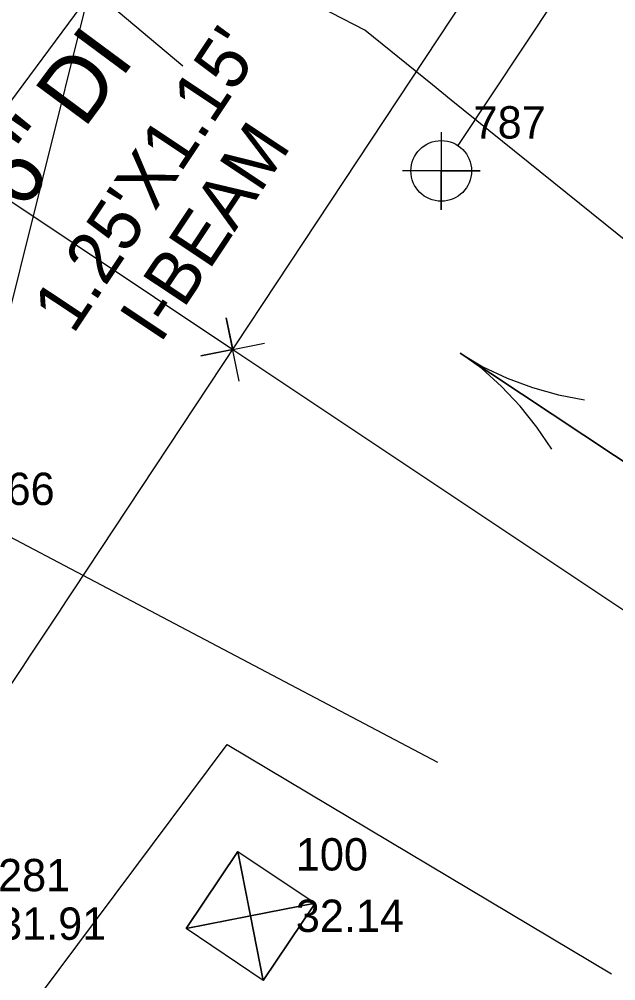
# Model space of a CAD drawing. Extents: x 2603627 to 2605187, y 896619 to 899063.
# Drawn here: x 2604574.8 to 2604621, y 898093.2 to 898167.5 of the extents above; entities that cross this region are included whole.
import ezdxf

# ---------------------------------------------------------------- set-up
doc = ezdxf.new("R2010")
doc.units = 0
for name, color, linetype in [('CTL Bench Mark CELL', 7, 'Continuous'), ('CTL Bench Mark Cogo Elevation', 7, 'Continuous'), ('CTL Bench Mark Cogo Number', 7, 'Continuous'), ('Default Symbol CELL', 7, 'Continuous'), ('Default Symbol Cogo Number', 7, 'Continuous'), ('Default Symbol Leader', 7, 'Continuous'), ('Exist DTM Drainline Cogo Elevation', 7, 'Continuous'), ('Exist Hydro Jurisdictional Stream or Body of Water', 7, 'Continuous'), ('Exist Hydro River Flow Arrow CELL', 7, 'Continuous'), ('Exist Property Corner CELL', 7, 'Continuous'), ('Exist Property Line', 7, 'Continuous'), ('Exist Property Tie Line', 7, 'Continuous'), ('Exist Right of Way Line', 7, 'Continuous'), ('Exist Structure Major Bridge Topo Leader', 7, 'Continuous'), ('Exist Structure Major Bridge Topo Text', 7, 'Continuous'), ('Exist Utilities Power Pole Cogo Elevation', 7, 'Continuous'), ('Exist Utilities Power Pole Cogo Number', 7, 'Continuous'), ('Exist Utilities Water UG Line SUE LOS C', 7, 'Continuous'), ('Exist Utilities Water UG Line SUE LOS C Text', 7, 'Continuous'), ('Exist Vegetation Woods Line', 7, 'Continuous')]:
    doc.layers.add(name, color=color, linetype=linetype)

# ---------------------------------------------------------------- blocks, each defined once
blk = doc.blocks.new('CTL BENCH MARK')
at = {"layer": 'CTL Bench Mark CELL'}
blk.add_line((0, 0), (0, 0), dxfattribs=at)
blk.add_lwpolyline([(-0.072, 0.07175), (0.07175, 0.07175), (0.07175, -0.072), (-0.072, -0.072)], close=True, dxfattribs=at)
for points in [[(0.07175, 0.07175), (-0.072, -0.072), (-0.000125, -0.000125), (0.07175, -0.072), (-0.072, 0.07175)], [(-0.000125, -0.000125), (0.07175, 0.07175), (-0.072, 0.07175), (-0.000125, -0.000125)], [(-0.000125, -0.000125), (-0.072, -0.072), (0.07175, -0.072), (-0.000125, -0.000125)]]:
    blk.add_lwpolyline(points, dxfattribs=at)
blk = doc.blocks.new('DEFAULT SYMBOL')
at = {"layer": 'Default Symbol CELL'}
blk.add_lwpolyline([(0, 0.06), (0, -0.06), (0, 0), (0.06, 0), (-0.06, 0)], dxfattribs=at)
blk.add_circle((0, 0), 0.0469, dxfattribs=at)

msp = doc.modelspace()

# ---------------------------------------------------------------- linework, layer by layer
at = {"layer": 'Default Symbol Leader'}
msp.add_line((2604608.764, 898157.759), (2604616.82, 898169.887), dxfattribs=at)
at = {"layer": 'Exist Hydro Jurisdictional Stream or Body of Water'}
for points in [[(2604623.046, 898149.352), (2604608.245, 898161.284), (2604606.782, 898162.463), (2604601.562, 898166.672), (2604579.029, 898178.3)], [(2604566.473, 898131.553), (2604607.177, 898110.112)]]:
    msp.add_lwpolyline(points, dxfattribs=at)
at = {"layer": 'Exist Hydro River Flow Arrow CELL'}
msp.add_line((2604617.268, 898136.202), (2604617.268, 898136.202), dxfattribs=at)
msp.add_lwpolyline([(2604616.005, 898134.295), (2604614.866, 898135.994), (2604613.572, 898137.616), (2604612.136, 898139.137), (2604610.599, 898140.53), (2604608.931, 898141.725), (2604625.605, 898130.68), (2604608.931, 898141.725), (2604610.682, 898140.655), (2604612.564, 898139.784), (2604614.524, 898139.054), (2604616.523, 898138.495), (2604618.532, 898138.109)], dxfattribs=at)
at = {"layer": 'Exist Property Corner CELL'}
msp.add_line((2604591.342, 898142.006), (2604591.342, 898142.006), dxfattribs=at)
msp.add_lwpolyline([(2604591.836, 898139.555), (2604590.847, 898144.456), (2604591.342, 898142.006), (2604588.891, 898141.511), (2604593.792, 898142.5)], dxfattribs=at)
at = {"layer": 'Exist Property Line'}
msp.add_line((2604591.342, 898142.006), (2604711.476, 898061.892), dxfattribs=at)
at = {"layer": 'Exist Property Tie Line'}
for p, q in [((2604598.893, 898244.519), (2604562.447, 898098.35)), ((2604549.449, 898169.943), (2604591.342, 898142.006))]:
    msp.add_line(p, q, dxfattribs=at)
at = {"layer": 'Exist Right of Way Line'}
msp.add_line((2604579.05, 898123.424), (2604689.463, 898290.329), dxfattribs=at)
msp.add_arc((2574512.676, 918013.514), 36050, 326.4094331, 326.5137949, dxfattribs=at)
at = {"layer": 'Exist Structure Major Bridge Topo Leader'}
msp.add_line((2604575.03, 898174.404), (2604587.483, 898163.92), dxfattribs=at)
at = {"layer": 'Exist Utilities Water UG Line SUE LOS C'}
msp.add_line((2604550.547, 898129.275), (2604590.411, 898183.073), dxfattribs=at)
at = {"layer": 'Exist Vegetation Woods Line'}
msp.add_lwpolyline([(2604559.057, 898068.863), (2604590.926, 898111.483), (2604620.628, 898093.762)], dxfattribs=at)

# ---------------------------------------------------------------- block references
at = {"layer": 'CTL Bench Mark CELL', "xscale": 50.000000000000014, "yscale": 50.00000000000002, "rotation": 56.07464692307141}
msp.add_blockref('CTL BENCH MARK', (2604592.723, 898098.238), dxfattribs=at)
at = {"layer": 'Default Symbol CELL', "xscale": 50, "yscale": 50}
msp.add_blockref('DEFAULT SYMBOL', (2604607.468, 898155.806), dxfattribs=at)

# ---------------------------------------------------------------- texts
at = {"layer": 'CTL Bench Mark Cogo Elevation'}
msp.add_text('32.14', height=2.5, dxfattribs=at).set_placement((2604596.223, 898096.988))
at = {"layer": 'CTL Bench Mark Cogo Number'}
msp.add_text('100', height=2.5, dxfattribs=at).set_placement((2604596.223, 898101.738))
at = {"layer": 'Default Symbol Cogo Number'}
msp.add_text('787', height=2.5, dxfattribs=at).set_placement((2604609.968, 898158.306))
at = {"layer": 'Exist DTM Drainline Cogo Elevation'}
msp.add_text('28.66', height=2.5, dxfattribs=at).set_placement((2604569.21, 898129.982))
at = {"layer": 'Exist Structure Major Bridge Topo Text'}
for s, p in [("1.25'X1.15'", (2604579.003, 898143.09)), ('I-BEAM', (2604585.726, 898142.368))]:
    msp.add_text(s, height=4, rotation=56.40944, dxfattribs=at).set_placement(p)
at = {"layer": 'Exist Utilities Power Pole Cogo Elevation'}
msp.add_text('31.91', height=2.5, dxfattribs=at).set_placement((2604573.201, 898096.382))
at = {"layer": 'Exist Utilities Power Pole Cogo Number'}
msp.add_text('281', height=2.5, dxfattribs=at).set_placement((2604573.201, 898100.132))
at = {"layer": 'Exist Utilities Water UG Line SUE LOS C Text'}
msp.add_text('6" DI', height=5, rotation=53.46186, dxfattribs=at).set_placement((2604575.113, 898152.605))

doc.saveas('drawing.dxf')
